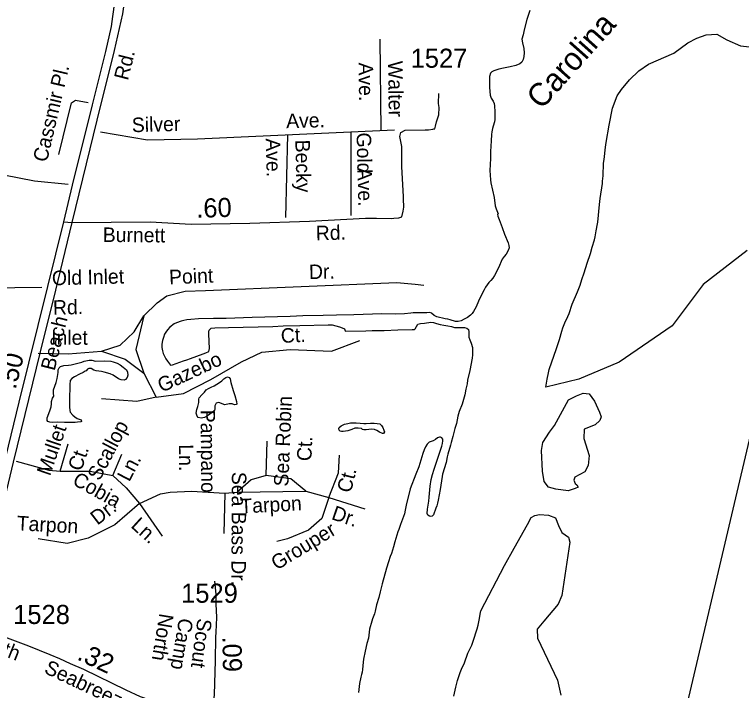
# Model space of a CAD drawing. Extents: x 2290055 to 2389491, y 66597 to 237875.
# Drawn here: x 2334145 to 2338909, y 116521 to 120949 of the extents above; entities that cross this region are included whole.
import ezdxf

# ---------------------------------------------------------------- set-up
doc = ezdxf.new("R2010")
doc.units = 0
for name, color, linetype in [('Exist Hydrographic Island Shore', 7, 'Continuous'), ('Exist Hydrographic Point Label', 7, 'Continuous'), ('Exist Hydrographic Pond Under 1500 Sq Ft', 7, 'Continuous'), ('Exist Road Non-System Type 51', 7, 'Continuous'), ('Exist Road Non-System Type 51 Label', 7, 'Continuous'), ('Exist Road Primary US Divided Attributed', 7, 'Continuous'), ('Exist Road Primary US Label', 7, 'Continuous'), ('Exist Road Primary US Mileage Hundredths English Label', 7, 'Continuous'), ('Exist Road Secondary Mileage Hundredths English Label', 7, 'Continuous'), ('Exist Road Secondary Type 51 Attributed', 7, 'Continuous'), ('Exist Road Secondary Type 51 Label', 7, 'Continuous'), ('Exist Road Secondary Type 51 Number Label', 7, 'Continuous'), ('Map Preparation Inset Cut Line', 7, 'Continuous')]:
    doc.layers.add(name, color=color, linetype=linetype)

msp = doc.modelspace()

# ---------------------------------------------------------------- linework, layer by layer
at = {"layer": 'Exist Hydrographic Island Shore'}
for points in [[(2337522, 120975.2), (2337503.2, 120915.8), (2337484.7, 120847.7), (2337477.7, 120815.4), (2337470.5, 120786.7)], [(2337627, 118507.1), (2337635.7, 118560.8), (2337643.5, 118601.8), (2337648.5, 118623), (2337697.2, 118760.1), (2337716.2, 118820), (2337732, 118875.6), (2337738.7, 118895.9), (2337751.7, 118929.1), (2337770.5, 118969.8), (2337779, 118990.1), (2337800, 119051.4), (2337835.5, 119131.2), (2337844.2, 119153.4), (2337852, 119175.6), (2337863.7, 119213.4), (2337878.7, 119256.3), (2337897.5, 119319.5), (2337920.7, 119383.6), (2337931, 119424.3), (2337945, 119472.1), (2337950, 119491.9), (2337958, 119530.8), (2337964.7, 119577.6), (2337968.7, 119588.9), (2337978.5, 119703.8), (2337983.5, 119743.5), (2337998, 119842.3), (2337999.5, 119857.7), (2338002.2, 119893.2), (2338006, 119975.2), (2338009.2, 120000), (2338017.2, 120079.2), (2338023, 120110.2), (2338042, 120223.9), (2338064.7, 120336.2), (2338093.7, 120415.6), (2338122.5, 120457.6), (2338176.2, 120520.1), (2338236.2, 120580.2), (2338299.2, 120623.3), (2338465.2, 120696.3), (2338557.5, 120763.5), (2338616, 120795.1), (2338678, 120816.4), (2338747.7, 120820.9), (2338814.2, 120783.4), (2338903, 120744.7), (2339000, 120733.1)], [(2337470.5, 120786.7), (2337473.5, 120764), (2337483.2, 120727.4), (2337485, 120699), (2337483.5, 120674), (2337479.2, 120653.7), (2337470, 120637.6), (2337456.5, 120625.1), (2337430, 120614.2), (2337393.2, 120606), (2337349, 120598.6), (2337318.5, 120590.5), (2337287, 120580.6), (2337273.5, 120573), (2337265, 120563.9), (2337257.2, 120542.5), (2337257.7, 120471.8), (2337262, 120421.2), (2337268.7, 120400), (2337283, 120380.4), (2337288.2, 120366.4), (2337291, 120349.8), (2337293.5, 120311), (2337293.5, 120277.5), (2337292.7, 120261.1), (2337290.5, 120245.5), (2337281.2, 120218.1), (2337277.5, 120203.1), (2337273, 120179.5), (2337270.7, 120162.1), (2337268.2, 120120.6), (2337265, 120052.5), (2337264.2, 120004.9), (2337260.7, 119926.6), (2337265.5, 119865.2), (2337267.7, 119845.3), (2337288.2, 119750.3), (2337295.2, 119696), (2337300.5, 119676.2), (2337314, 119644.3), (2337310, 119641.7), (2337313, 119626.9), (2337320.7, 119605.2), (2337341.2, 119554.3), (2337356, 119510.6), (2337379.7, 119453.3), (2337385.2, 119435.6), (2337386.5, 119420.5), (2337381.2, 119402.6), (2337366.7, 119380), (2337354, 119364.8), (2337341.5, 119345.6), (2337316.2, 119289.5), (2337289.7, 119238.8), (2337280.2, 119222.7), (2337267.5, 119206.7), (2337254.2, 119192.5), (2337242.7, 119178.1), (2337232.7, 119162.7), (2337223, 119145.5), (2337203.2, 119109.2), (2337185.7, 119072.1), (2337169.5, 119032.9), (2337153.5, 119003.5), (2337144, 118990.2), (2337132.7, 118979.2), (2337113, 118963.1), (2337092.2, 118952.1), (2337071.5, 118942.6), (2337051.5, 118937.9), (2337034.7, 118937.8), (2337000.5, 118948.8), (2336985.5, 118952.3), (2336967.2, 118955.3), (2336912, 118969.5), (2336894.5, 118977.3), (2336878, 118991.6), (2336867.7, 118996.1), (2336847.5, 118995.4), (2336831.5, 118993.9), (2336794, 118994.9), (2336758.2, 118994.5), (2336741.5, 118993.5), (2336700, 118988.9), (2336643.5, 118986.9), (2336552.7, 118987.1), (2336368.7, 118980.5), (2336255.7, 118979.3), (2336168, 118976.8), (2336035.2, 118974.8), (2335951, 118971.2), (2335701.7, 118964.9), (2335532, 118958.5), (2335493.2, 118957.4), (2335448.7, 118957.3), (2335350.5, 118954.3), (2335301.5, 118951.8), (2335275, 118949.2), (2335254.5, 118945.4), (2335237, 118940.1)], [(2338947.2, 119402.3), (2338658.7, 119179.6), (2338455.2, 118909), (2338107.2, 118670.4), (2337844.2, 118559), (2337627, 118507.1)], [(2335237, 118940.1), (2335206.2, 118928.3), (2335191.7, 118921.6), (2335163.2, 118899.9), (2335148.5, 118884.3), (2335137.5, 118868.9), (2335128.5, 118854.3), (2335120.5, 118834), (2335114.2, 118812.8), (2335110.2, 118788.9), (2335110.5, 118768.2), (2335114.7, 118745.9), (2335120, 118727.3), (2335127, 118710.7), (2335136.2, 118693.9), (2335147, 118676.9), (2335168, 118652.2), (2335180.7, 118653.4), (2335253.5, 118679.4), (2335274.5, 118687.6), (2335297.5, 118695.3), (2335340, 118711.7), (2335382.2, 118726.4), (2335399.7, 118731.7), (2335418.7, 118742.3), (2335422, 118761.5), (2335418.7, 118855.9), (2335419.5, 118874.7), (2335420.5, 118880.4), (2335433.7, 118893.7), (2335457.5, 118895.3), (2335546.7, 118898.4), (2335838.5, 118905.7), (2335904.7, 118909.1), (2336014.7, 118912.7), (2336201, 118916.4), (2336227, 118915.7), (2336275, 118903), (2336293.2, 118897.1), (2336308.5, 118890.1), (2336311.5, 118876.9), (2336314, 118875.1), (2336446.7, 118876.5), (2336488.2, 118878.2), (2336567, 118879.5), (2336657.5, 118882.7), (2336751.5, 118885), (2336765.7, 118886.2), (2336771, 118888.9), (2336779.5, 118905.8), (2336789, 118919.8), (2336806, 118924), (2336831.5, 118927.2), (2336873.5, 118933.9), (2336891, 118931.7)], [(2336891, 118931.7), (2336909.7, 118923.8), (2336933.7, 118918.1), (2336958.2, 118913.8), (2336985.5, 118910.1), (2337008.7, 118904.6), (2337027.7, 118899.1), (2337043.7, 118897.7), (2337093.5, 118897.8), (2337109, 118893.4), (2337119.5, 118885.1), (2337122.2, 118869.9), (2337123, 118835.8), (2337128.5, 118817.8), (2337137.7, 118796.1), (2337145.5, 118767.3), (2337147, 118745.6), (2337146.2, 118719), (2337143.7, 118698.7), (2337129.2, 118617.1), (2337114.7, 118553.2), (2337111.7, 118530.4), (2337103, 118494.4), (2337096.5, 118458.5), (2337078.7, 118397.1), (2337060, 118349.2), (2337054.7, 118332.4), (2337051, 118317.6), (2337041.5, 118269.9), (2337031.7, 118237.7), (2337018.7, 118183.8), (2337006.2, 118145), (2337003.2, 118128.1), (2336985.2, 118068.3), (2336981, 118051.2), (2336974, 118015), (2336950.2, 117938.3), (2336947, 117922.4), (2336934.2, 117837.2), (2336921, 117766.6), (2336917.2, 117748.1), (2336912.5, 117729.9), (2336907, 117714.6), (2336890.2, 117672.3), (2336881.2, 117663.4), (2336872.5, 117660.8), (2336864.2, 117662.6), (2336854.7, 117669.5), (2336849.5, 117679.4), (2336850.7, 117707.6), (2336860.2, 117761), (2336863.5, 117787.6), (2336868.7, 117858.2), (2336875.7, 117903.1), (2336884.5, 117935.3), (2336895, 117969.5), (2336929, 118069.6), (2336945, 118121.5), (2336949.5, 118139.5), (2336952.5, 118155.9), (2336951, 118166.9), (2336945, 118175.6), (2336937.7, 118180), (2336929.2, 118180.3), (2336917.2, 118175.6), (2336903, 118164.9), (2336889.5, 118156.7), (2336863.2, 118146.4), (2336849.2, 118134.7), (2336838.5, 118117.1), (2336830.2, 118096.9), (2336821.5, 118072.4), (2336794.5, 117985.9), (2336774.5, 117937.6), (2336738.5, 117841), (2336711.5, 117735), (2336706, 117702.6), (2336700, 117678.2), (2336682, 117625), (2336675, 117607.2), (2336664.5, 117575), (2336658, 117559.1), (2336638.2, 117494.5), (2336628.7, 117460.6), (2336614.7, 117417.9), (2336607.2, 117397.8), (2336597, 117362.3), (2336583.7, 117320.8), (2336555, 117218.8), (2336541.2, 117165.8), (2336533, 117128.9), (2336517.5, 117080.6), (2336509.5, 117040.9), (2336504.2, 117022.4), (2336491.7, 116990.3), (2336486.5, 116974.7), (2336471.5, 116921.2), (2336468.2, 116883.6), (2336465.2, 116862.2), (2336455, 116828.1)], [(2337683, 118256.6), (2337776.2, 118423.7), (2337828.2, 118451.5), (2337870.7, 118469.4), (2337912, 118463.5), (2337945, 118415.7), (2337979, 118344.1), (2337989.5, 118314.3), (2337980, 118288.4), (2337951.2, 118260.6), (2337878.2, 118232.7), (2337875, 118171.1), (2337911, 118059.7), (2337903.7, 117994.1), (2337883.5, 117952.3), (2337817.7, 117918.5), (2337810.2, 117898.6), (2337819.7, 117876.7), (2337830.5, 117866.7), (2337839, 117852.8), (2337818.7, 117842.9), (2337773.2, 117828.9), (2337692.5, 117838.9), (2337643.7, 117852.8), (2337615.2, 117890.6), (2337605.5, 117958.2), (2337599.2, 118093.5), (2337606.7, 118145.2), (2337650.2, 118212.8), (2337683, 118256.6)], [(2337024.5, 116484.3), (2337037.2, 116541.5), (2337048.5, 116585.4), (2337065.2, 116637.5), (2337074, 116660.6), (2337093, 116702.6), (2337116, 116764.5), (2337142, 116818.4), (2337151.2, 116843.3), (2337177.2, 116924.8), (2337183.2, 116948.4), (2337189.2, 116982.1), (2337199.5, 117031.7), (2337201.7, 117042.4), (2337355.2, 117339.6), (2337420, 117453), (2337506, 117608.1), (2337531.2, 117653.9), (2337555.7, 117667.8), (2337586.5, 117673.8), (2337643.7, 117669.8), (2337691.5, 117651.9), (2337709.5, 117602.2), (2337732.7, 117556.4), (2337776.2, 117524.6), (2337783.7, 117492.8), (2337732.7, 117142.7), (2337708.5, 117087), (2337614, 116975.6), (2337569.5, 116921.9), (2337572.7, 116864.2), (2337703.2, 116587.7), (2337725.5, 116490.3)], [(2336455, 116828.1), (2336443, 116777), (2336432, 116725.1), (2336429.5, 116705.8), (2336426, 116658.9), (2336423.5, 116640.9), (2336420, 116624.1), (2336415.5, 116608.5), (2336406.7, 116567.2), (2336403.2, 116546.9), (2336400.5, 116507)]]:
    msp.add_lwpolyline(points, dxfattribs=at)
at = {"layer": 'Exist Hydrographic Pond Under 1500 Sq Ft'}
for points in [[(2334472.5, 118276.2), (2334427.2, 118277.6), (2334391.5, 118277), (2334376, 118278.3), (2334364, 118283.2), (2334359.5, 118288.2), (2334360.2, 118306.1), (2334369.2, 118334.9), (2334379, 118359.1), (2334384.5, 118378.6), (2334387.5, 118398.2), (2334386.7, 118414.5), (2334394, 118435.3), (2334402.5, 118449.5), (2334401, 118467.8), (2334401.7, 118490.2), (2334408.5, 118514.9), (2334417.2, 118538), (2334425, 118564.4), (2334431.5, 118603.4), (2334431, 118620.4), (2334437.2, 118635.3), (2334446.7, 118643.6), (2334468.5, 118648.6), (2334499.7, 118651.4), (2334517.5, 118654), (2334586.5, 118671.5), (2334601, 118677.9), (2334635, 118685.2), (2334651.5, 118683.7), (2334676.7, 118678.6), (2334732.2, 118680), (2334776, 118678.2), (2334792, 118674.7), (2334817.7, 118665.5), (2334838.2, 118653), (2334858.2, 118638.8), (2334878, 118620.7), (2334885.7, 118607), (2334888.5, 118586.7), (2334883.7, 118571.7), (2334871.5, 118558.7), (2334864.2, 118554.3), (2334843.5, 118554.8), (2334826.7, 118563.3), (2334791.7, 118585.7), (2334772, 118594.5), (2334733.7, 118606.5), (2334714.5, 118610.5), (2334680.7, 118614.5), (2334664.5, 118618.8), (2334646.5, 118629), (2334631.2, 118630), (2334624.5, 118626.6), (2334613.7, 118615.5), (2334607.5, 118612.7), (2334595.5, 118603.3), (2334571, 118592.9), (2334537.7, 118574.8), (2334520, 118563.5), (2334510.2, 118551.4), (2334506.7, 118524.8), (2334505, 118421.3), (2334506, 118379.8), (2334507.5, 118354.4), (2334510, 118344.2), (2334528, 118324.1), (2334539.5, 118313.3), (2334556.7, 118302.3), (2334576.2, 118296.8), (2334581, 118294.5), (2334583.7, 118283.7), (2334580.5, 118279.7), (2334557.2, 118277.5), (2334541.7, 118276.7), (2334472.5, 118276.2)], [(2335367.5, 118305), (2335348.2, 118309.2), (2335342, 118316.6), (2335336.5, 118337.1), (2335340.2, 118361.8), (2335347, 118382), (2335353.2, 118406.3), (2335353.5, 118429), (2335355.5, 118437.2), (2335372, 118456.9), (2335389.5, 118474.6), (2335401.7, 118489.4), (2335415.5, 118499.7), (2335433.7, 118507.4), (2335454, 118517.1), (2335472, 118527), (2335488.7, 118537.7), (2335503.7, 118549.1), (2335517.7, 118562.1), (2335529.5, 118571.3), (2335541, 118575.6), (2335551.2, 118571.7), (2335559, 118561.5), (2335563, 118537.4), (2335578.5, 118485.5), (2335589.5, 118452.5), (2335600.2, 118414), (2335602, 118396.8), (2335598.7, 118393.1), (2335587.2, 118392.7), (2335572.2, 118398), (2335552.5, 118397.7), (2335522.7, 118391.9), (2335507, 118397.5), (2335491.2, 118405.6), (2335482, 118407.7), (2335465.7, 118402.2), (2335457.5, 118385.5), (2335457.7, 118363.6), (2335456.5, 118355.6), (2335441.5, 118342.6), (2335425.7, 118331.8), (2335409.5, 118319.1), (2335390.2, 118309.6), (2335367.5, 118305)], [(2336556.7, 118204.3), (2336537, 118212.8), (2336519, 118223.2), (2336505.2, 118229.8), (2336486.2, 118232.6), (2336467.5, 118229.5), (2336450.5, 118228.2), (2336433.5, 118228.5), (2336426.2, 118230.6), (2336418, 118236.4), (2336397.2, 118240), (2336375.5, 118238.5), (2336355, 118229.4), (2336330, 118220.6), (2336298.2, 118216.5), (2336287.2, 118216.9), (2336279, 118220.2), (2336272, 118226.6), (2336269.7, 118235.8), (2336273.5, 118243.6), (2336285.7, 118253.6), (2336306.7, 118265.9), (2336329, 118270.6), (2336347.7, 118273.3), (2336369, 118274.2), (2336384, 118274.1), (2336410.2, 118272.4), (2336434.2, 118269), (2336450.5, 118268.9), (2336477.2, 118271.1), (2336502.5, 118272), (2336522.2, 118270.2), (2336538.5, 118266.7), (2336550, 118256.4), (2336559.5, 118243.5), (2336566.5, 118225.3), (2336569.5, 118214.1), (2336563, 118204.6), (2336556.7, 118204.3)]]:
    msp.add_lwpolyline(points, dxfattribs=at)
at = {"layer": 'Exist Road Non-System Type 51'}
for points in [[(2336539.9, 120787.1), (2336545.9, 120190.2)], [(2330169.1, 120128.4), (2330269.6, 120191.3), (2330298.9, 120233.2), (2330822.2, 120342.1), (2330960.4, 120354.6), (2331144.6, 120367.2), (2331571.6, 120367.2), (2331680.4, 120375.6), (2331948.4, 120400.7), (2332174.4, 120425.9), (2332295.8, 120421.7), (2332417.2, 120379.8), (2332547, 120287.6), (2332672.6, 120220.6), (2332844.2, 120161.9), (2333154, 120094.9), (2333472.2, 120027.9), (2333882.5, 119935.7), (2334276, 119860.3), (2334497.4, 119837.7)], [(2334435.1, 120032.1), (2334518.8, 120371.4), (2334543.9, 120388.2), (2334628.9, 120373.1)], [(2334709.7, 120180.4), (2335015.7, 120128.4), (2335344.8, 120134.2), (2336636.1, 120194.4)], [(2335933.8, 120161.6), (2335921.7, 119620)], [(2336349.4, 120181), (2336349.4, 119631.4)], [(2334323.8, 119159.6), (2333788.7, 119153.1), (2333713.3, 119528.1), (2333311.4, 119521.8), (2333275.9, 119513.4), (2333254.9, 119492.5), (2333192.1, 119142.7), (2333788.7, 119153.1)], [(2334299.7, 118731.4), (2334496, 118725.6), (2334715.4, 118742.9), (2334836.7, 118783.4), (2334929.1, 118870), (2334992.6, 118974), (2335079.2, 119060.7), (2335142.7, 119106.9), (2335263.9, 119135.8), (2335396.7, 119141.6), (2336649.6, 119193.6), (2336770.9, 119182), (2336828.6, 119176.2)], [(2334992.6, 118974), (2334940.6, 118754.5), (2334992.6, 118598.5)], [(2335073.4, 118442.5), (2335252.4, 118465.6), (2335431.4, 118558), (2335633.4, 118673.6), (2335766.2, 118737.1), (2335951, 118754.5), (2336222.4, 118742.9), (2336407.1, 118812.3)], [(2334715.4, 118742.9), (2334871.3, 118690.9), (2334992.6, 118598.5), (2335073.4, 118442.5), (2334946.4, 118413.6), (2334715.4, 118430.9)], [(2335795.1, 117929.4), (2335800.9, 118154.7)], [(2334155.4, 118021.9), (2334369, 117964.1), (2334444.1, 117958.3), (2334496, 118137.4)], [(2334444.1, 117958.3), (2334640.4, 117958.3), (2334790.5, 117929.4), (2334848.2, 118068.1)], [(2336205, 117785), (2336268.5, 117946.7), (2336274.3, 118062.3)], [(2334790.5, 117929.4), (2334877.1, 117848.5), (2334963.7, 117744.5), (2334802, 117605.9), (2334628.8, 117519.2), (2334490.3, 117484.5), (2334299.7, 117513.4)], [(2336054.9, 117825.4), (2335956.8, 117906.3), (2335795.1, 117929.4), (2335697, 117900.5), (2335604.6, 117819.6)], [(2334963.7, 117744.5), (2335102.3, 117808.1), (2335165.8, 117819.6), (2335304.3, 117825.4), (2335523.7, 117813.9), (2335604.6, 117819.6), (2336054.9, 117825.4), (2336205, 117785), (2336441.8, 117709.9)], [(2335523.7, 117813.9), (2335518, 117548.1)], [(2336205, 117785), (2336158.8, 117646.3), (2336072.2, 117571.2), (2335933.7, 117513.4), (2335864.4, 117496.1)], [(2334963.7, 117744.5), (2335113.8, 117530.8)], [(2335467.5, 116901.9), (2335470, 116998), (2335467.5, 117089.1), (2335467.5, 117152.3), (2335457.4, 117235.8)]]:
    msp.add_lwpolyline(points, dxfattribs=at)
at = {"layer": 'Exist Road Primary US Divided Attributed'}
for points in [[(2334523.5, 119587), (2334685.9, 120257.1), (2334799.5, 120712.5), (2334854.5, 120954.2), (2334871.5, 121075.2), (2334878, 121269.7), (2334835.2, 121611.3), (2334709.3, 122310), (2334646.5, 122661.5), (2334542.7, 123249.2), (2334508.9, 123436.4)], [(2334526.2, 122980.8), (2334562.7, 122810.4), (2334605.9, 122554.4), (2334663.8, 122225.2), (2334717.7, 121927.1), (2334745.2, 121772.4), (2334774.3, 121604.4), (2334802.2, 121443.6), (2334810.4, 121378.3), (2334813.2, 121270.8), (2334801.4, 121030.8), (2334787, 120936), (2334778.8, 120870.3), (2334741.5, 120705.8), (2334654.3, 120356.9), (2334522.3, 119830.8), (2334466.3, 119591.7)], [(2334466.3, 119591.7), (2334361.5, 119167.8), (2334174.1, 118409.4), (2334050.7, 117905.9), (2333955.7, 117519.8), (2333800.5, 116886), (2333680.3, 116393.8)], [(2333877, 116945.7), (2334035.3, 117594.3), (2334139.4, 118017.3), (2334315.2, 118739.4), (2334415.2, 119144.1), (2334523.5, 119587)]]:
    msp.add_lwpolyline(points, dxfattribs=at)
at = {"layer": 'Exist Road Secondary Type 51 Attributed'}
for points in [[(2334523.5, 119587), (2335034.9, 119590.5), (2335302.1, 119575.8), (2335686.6, 119583), (2336077.9, 119595.2), (2336445.6, 119615.2), (2336517.2, 119615.2), (2336618, 119613), (2336631.4, 119615.2), (2336662.7, 119617.4), (2336682.9, 119624.2), (2336691.8, 119660), (2336696.3, 119686.9), (2336696.3, 119707), (2336694.1, 119722.7), (2336694.1, 119756.3), (2336682.9, 119951.2), (2336682.9, 120083.3), (2336669.5, 120150.5), (2336676.9, 120176.7), (2336705.3, 120191.6), (2336836.6, 120194.6), (2336859, 120194.6), (2336885.9, 120197.6), (2336893.3, 120199.1), (2336899.3, 120200.6), (2336903.8, 120218.5), (2336911.2, 120246.8), (2336918.7, 120272.2), (2336926.2, 120291.6), (2336927.6, 120340.9), (2336923.2, 120366.3), (2336926.2, 120432)], [(2334466.3, 119591.7), (2334523.5, 119587)], [(2335448.1, 116428.8), (2335404.5, 116435.8), (2335322.7, 116434.8), (2335198.9, 116436.9), (2335106.1, 116444.3), (2335033.1, 116457.5), (2334970.9, 116478), (2334876.4, 116522.8), (2334600.2, 116658.4), (2334513, 116694.4), (2334442.4, 116727.5), (2334379.2, 116754.6), (2334238, 116811.7), (2333877, 116945.7)], [(2335448.1, 116428.8), (2335456.5, 116491.4), (2335462.4, 116717.3), (2335464.9, 116869), (2335467.5, 116901.9)]]:
    msp.add_lwpolyline(points, dxfattribs=at)
at = {"layer": 'Map Preparation Inset Cut Line'}
msp.add_lwpolyline([(2318953.4, 149726.2), (2325417.5, 149726.2), (2346393.7, 149726.2), (2338303.7, 115381.1), (2324894.8, 115381.1)], close=True, dxfattribs=at)

# ---------------------------------------------------------------- texts
at = {"layer": 'Exist Hydrographic Point Label'}
msp.add_text('Carolina', height=150, rotation=48.3368, dxfattribs=at).set_placement((2337598.8, 120320.8))
at = {"layer": 'Exist Road Non-System Type 51 Label'}
for s, rotation, p in [('Ave.', 270.7134, (2336400, 120634.3)), ('Walter', 270.7134, (2336593.3, 120644.7)), ('Cassmir Pl.', 76.8424, (2334357.1, 119977)), ('Ave.', 1.4982, (2335926.3, 120204.3)), ('Silver', 1.4978, (2334915.2, 120177.9)), ('Gold', 271.3846, (2336386.4, 120175)), ('Ave.', 271.3705, (2335791.5, 120136.9)), ('Becky', 271.3705, (2335985.2, 120128.1)), ('Ave.', 271.3846, (2336392.4, 119944.6)), ('Old Inlet', 1.4589, (2334391.4, 119175.1)), ('Point', 2.3935, (2335159.9, 119181)), ('Dr.', 1.4358, (2336075.9, 119215.5)), ('Rd.', 1.4589, (2334398.1, 118981.8)), ('Ct.', 2.9834, (2335892.7, 118796.9)), ('Gazebo', 25.0576, (2335110.3, 118470.3)), ('       Sea Robin ', 87.6903, (2335929.4, 117608.7)), ('Pampano ', 270.543, (2335364.2, 118359)), ('Mullet', 71.0954, (2334377.7, 117921.4)), ('Scallop ', 62.3605, (2334702.3, 117888.5)), ('Ct.', 87.6903, (2336090.4, 118021.9)), ('Ct.', 71.0954, (2334582.1, 117951.9)), ('Ln.', 270.543, (2335222.1, 118133)), ('Ln.', 62.3605, (2334897.1, 117882.9)), ('Ct.', 75.8036, (2336348.4, 117810)), ('Cobia', 330.9277, (2334518, 117874.5)), ('Sea Bass Dr.', 269.7375, (2335569.6, 117952.9)), ('Tarpon', 2.9441, (2335627.7, 117680.1)), ('Dr.', 37.5114, (2334688.4, 117599.9)), ('Dr.', 341.3601, (2336216.7, 117644)), ('Tarpon', 356.939, (2334158.1, 117570.5)), ('Ln.', 317.7098, (2334902.4, 117593.8)), ('Grouper', 31.3983, (2335863.5, 117305.3))]:
    msp.add_text(s, height=95, rotation=rotation, dxfattribs=at).set_placement(p)
msp.add_text('Inlet', height=95, dxfattribs=at).set_placement((2334385.3, 118785.3))
at = {"layer": 'Exist Road Primary US Label'}
for s, rotation, p in [('Rd.', 75.9248, (2334887.8, 120513.1)), ('Beach', 76.0127, (2334407.6, 118610.8))]:
    msp.add_text(s, height=95, rotation=rotation, dxfattribs=at).set_placement(p)
at = {"layer": 'Exist Road Primary US Mileage Hundredths English Label'}
msp.add_text('.50', height=125, rotation=76.0512, dxfattribs=at).set_placement((2334152.3, 118488.4))
at = {"layer": 'Exist Road Secondary Mileage Hundredths English Label'}
for s, rotation, p in [('.60', 1.6073, (2335337.8, 119617.3)), ('.09', 270.8711, (2335507.8, 116873.1)), ('.32', 334.8524, (2334548.4, 116725.7))]:
    msp.add_text(s, height=125, rotation=rotation, dxfattribs=at).set_placement(p)
at = {"layer": 'Exist Road Secondary Type 51 Label'}
for s, rotation, p in [('Rd.', 1.5235, (2336120.7, 119469.4)), ('Burnett', 359.5263, (2334723.3, 119459.1)), ('North', 260.5774, (2335095.5, 117029.6)), ('Camp', 260.3713, (2335223.8, 116999.1)), ('Scout', 262.0531, (2335345.5, 116996.7)), ('North', 338.4827, (2333870.8, 116827.3)), ('Seabreeze', 334.8956, (2334333.2, 116637.8))]:
    msp.add_text(s, height=95, rotation=rotation, dxfattribs=at).set_placement(p)
at = {"layer": 'Exist Road Secondary Type 51 Number Label'}
for s, p in [('1527', (2336740.8, 120600.3)), ('1529', (2335236.9, 117095.3)), ('1528', (2334136.5, 116956.1))]:
    msp.add_text(s, height=125, dxfattribs=at).set_placement(p)

doc.saveas('drawing.dxf')
